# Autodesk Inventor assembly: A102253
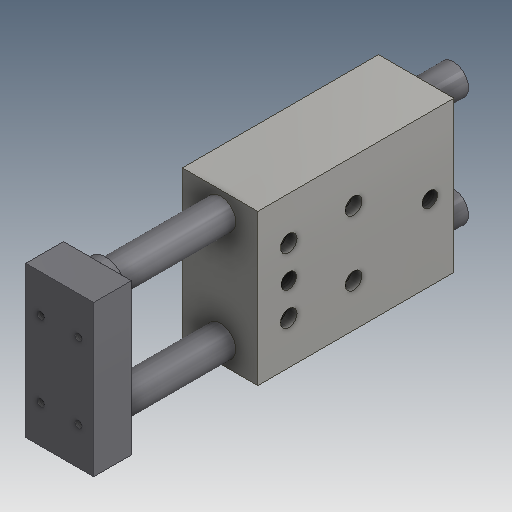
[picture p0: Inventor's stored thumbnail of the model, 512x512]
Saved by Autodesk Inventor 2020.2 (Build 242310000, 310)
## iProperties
Created: 2000-01
Part Number: A102253
Document SubType Name: Assembly
Designer: sspink
Mass: 3557.45 g
Surface Area: 1179.25 cm^2
Volume: 815.905 cm^3
Density: 4.36013 g/cm^3
Control State: 0
Master: False
Checked Out: False
Shininess: 0.0
Length Units: 11269
Angle Units: 11279
Time Units: 11290
Mass Units: 11283
Length Display Precision: 3
Angle Display Precision: 2
Compacted: True
Dimensions: 100x261x50 mm
Mass: 3,557 kg
Density: 0.0
Volumn: 0.0
Area: 0.0
PropertySet Name: Model Information
Author: sspink
Revision Number: -
Title: A102253
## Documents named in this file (3)
- D:\07 - DEMODATEN\OTX 2019 - Dataset - UPDATE - Dez2019\Designs\07-Packing machine\A102253.iam
- D:\07 - DEMODATEN\OTX 2019 - Dataset - UPDATE - Dez2019\Designs\07-Packing machine\Parts\ADSK-011755.ipt
- D:\07 - DEMODATEN\OTX 2019 - Dataset - UPDATE - Dez2019\Designs\07-Packing machine\Parts\ADSK-011756.ipt
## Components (2 placed, 2 different names)
1. ADSK-011755:1 — Flush:1, Mate:1, Mate:2, Mate:3
2. ADSK-011756:1 — Mate:1, Mate:2, Mate:3
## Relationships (4: Mate 3, Flush 1)
- Flush:1: ADSK-011755:1
- Mate:1: ADSK-011755:1 ↔ ADSK-011756:1
- Mate:2: ADSK-011755:1 ↔ ADSK-011756:1
- Mate:3: ADSK-011755:1 ↔ ADSK-011756:1
